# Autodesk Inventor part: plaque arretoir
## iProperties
Created: 2011-01
Part Number: plaque arretoir
Document SubType Name: Modeling
Designer: eric
Density: 1 g/cm^3
Mass: 0.154353 g
Surface Area: 6.96093 cm^2
Volume: 0.154353 cm^3
Author: eric
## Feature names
1. Base1
